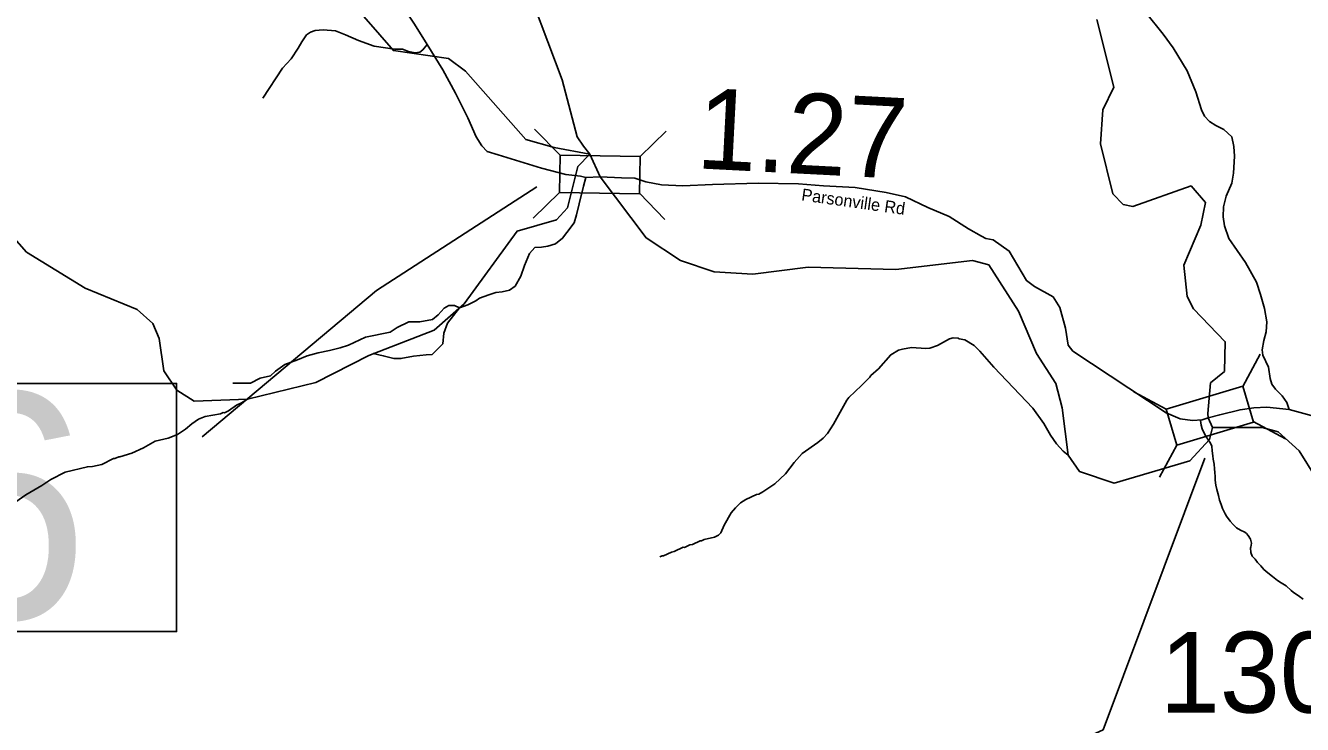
# Model space of a CAD drawing. Extents: x 1248224 to 1454986, y 825081 to 985870.
# Drawn here: x 1300750 to 1308662, y 901429 to 905757 of the extents above; entities that cross this region are included whole.
import ezdxf

# ---------------------------------------------------------------- set-up
doc = ezdxf.new("R2010")
doc.units = 0
for name, color, linetype in [('Exist Hydrographic Creek Single Shore', 7, 'Continuous'), ('Exist Hydrographic Misc Water Feature', 7, 'Continuous'), ('Exist Road Non-System Type 51', 7, 'Continuous'), ('Exist Road Secondary Mileage Hundredths English Label', 7, 'Continuous'), ('Exist Road Secondary Structure Standard Bridge CELL', 7, 'Continuous'), ('Exist Road Secondary Structure Standard Bridge Number Label', 7, 'Continuous'), ('Exist Road Secondary Type 41 Attributed', 7, 'Continuous'), ('Exist Road Secondary Type 51 Attributed', 7, 'Continuous'), ('Exist Road Secondary Type 51 Label', 7, 'Continuous'), ('Exist Road Secondary Type 51 Number Label', 7, 'Continuous')]:
    doc.layers.add(name, color=color, linetype=linetype)

msp = doc.modelspace()

# ---------------------------------------------------------------- linework, layer by layer
at = {"layer": 'Exist Hydrographic Creek Single Shore'}
for points in [[(1304310.6, 904820.9), (1304247, 904960.2), (1304207.5, 905010.9), (1304167.5, 905067.4), (1304075.6, 905420.6), (1303808.5, 906128.4), (1303495.2, 906669.2), (1303356.3, 907192.5), (1303303.2, 907311.5), (1303171.6, 907397.6)], [(1308103.7, 903268.3), (1308084.7, 903193.2), (1307964.7, 903061), (1307494.7, 902922.7), (1307279.7, 902996), (1307209.7, 903095.9), (1307172.7, 903388.7), (1307133.7, 903540.5), (1307013.7, 903726.8), (1306902.6, 903988.4), (1306717.7, 904274.4), (1306617.6, 904302.7), (1306141.7, 904246.6), (1305599.6, 904260.7), (1305256.6, 904218.3), (1305015.6, 904233), (1304808.6, 904302.8), (1304594.6, 904441.8), (1304310.6, 904820.9)], [(1308078, 903328.5), (1308075.9, 903354.2), (1308092.7, 903544.3), (1308177.7, 903614.8), (1308182.7, 903798.5), (1308175.4, 903806.1)], [(1308103.7, 903268.3), (1308078, 903328.5)], [(1309612, 901427.1), (1309422.7, 901551.2), (1309263.8, 901889.2), (1309225.8, 902047.6), (1309237.8, 902224.6), (1309323.8, 902331.2), (1309306.8, 902656.5), (1309333.7, 902754.4), (1309301.7, 902824), (1308852.8, 902882.4), (1308746.8, 902953.4), (1308641.7, 903122.9), (1308511.7, 903240.5), (1308411.7, 903268.7), (1308103.7, 903268.3)]]:
    msp.add_lwpolyline(points, dxfattribs=at)
at = {"layer": 'Exist Hydrographic Misc Water Feature'}
msp.add_line((1304247, 904960.2), (1304171.5, 904883.6), dxfattribs=at)
for points in [[(1304247, 904960.2), (1304025.6, 905001.5), (1303850.5, 905050.9), (1303476.5, 905475.2), (1303369.6, 905553), (1303029.5, 905602.4), (1302761.5, 905909.9), (1302058.5, 906176.7), (1301993.5, 906269.8), (1301955.5, 906405.3), (1301898.5, 906445.8), (1301382.5, 906518.4), (1301292.5, 906579.4), (1301212.4, 906722.2), (1300623.4, 907242.8), (1300187.4, 907461.7), (1299720.4, 907858.5), (1299520.4, 907911.7)], [(1308182.7, 903798.5), (1307986.6, 904002.7), (1307946.7, 904079), (1307926.7, 904273.1), (1308032.7, 904520.5), (1308060.7, 904661.1), (1307971.7, 904764.6), (1307609.7, 904637.3), (1307551.6, 904648.4), (1307486.6, 904715.3), (1307410.6, 905025.4), (1307423.7, 905235.2), (1307493.7, 905375), (1307386.7, 905794)], [(1299447.5, 904919.1), (1299983.5, 904806.7), (1300618.5, 904508.3), (1300756.5, 904354.5), (1301118.5, 904130.6), (1301440.6, 903999.4), (1301538.6, 903912), (1301578.6, 903819.3), (1301606.5, 903618.5), (1301687.5, 903498.7), (1301794.6, 903431), (1302125.6, 903443.6), (1302547.5, 903547.1), (1302876.5, 903714.5), (1303280.6, 903870.6), (1303467.6, 904034.2), (1303795.6, 904484), (1304038.6, 904554.6), (1304107.6, 904628.7), (1304171.5, 904883.6)], [(1304678.9, 902465.9), (1304695.1, 902473.5), (1304703.1, 902473.2), (1304751.7, 902495.8), (1304767.9, 902499.3), (1304824.6, 902525.7), (1304832.6, 902525.5), (1304865.1, 902540.5), (1304881.2, 902544), (1304929.8, 902566.7), (1304937.8, 902566.4), (1304954, 902574), (1305018.5, 902588.1), (1305042.9, 902601.3), (1305057.3, 902615), (1305078.6, 902662.3), (1305122.8, 902739), (1305147.7, 902770.3), (1305180.6, 902801.4), (1305213.2, 902822.4), (1305278, 902852.5), (1305294.1, 902856), (1305318.5, 902869.3), (1305392, 902919.2), (1305457.7, 902981.3), (1305511.8, 903051.7), (1305561.3, 903106.3), (1305659.3, 903175.4), (1305692, 903202.5), (1305718.9, 903231.7), (1305756.5, 903288.6), (1305838.7, 903438.2), (1305851.2, 903453.7), (1305928.5, 903528.3), (1305980.8, 903580), (1305987.1, 903589.8), (1306034.2, 903630.4), (1306110.7, 903718.2), (1306159.5, 903746.8), (1306183.8, 903754), (1306240, 903762.5), (1306328, 903757.9), (1306352, 903759.2), (1306400.5, 903775.8), (1306473.7, 903817.6), (1306497.9, 903822.9), (1306527.8, 903822.1), (1306533.7, 903817.9), (1306569.5, 903810.8), (1306626.5, 903775.3), (1306661.6, 903740.2), (1306748.8, 903641.8), (1306991.8, 903386.8), (1307059.2, 903292.9), (1307101.1, 903219.7), (1307137.7, 903166.7), (1307178.4, 903121.5), (1307209.7, 903095.9)], [(1300654.1, 902782.1), (1300752, 902851.3), (1300849.7, 902908.4), (1300906.8, 902946.8), (1300996.1, 902992.2), (1301133.1, 903024.3), (1301165.2, 903027.3), (1301221.6, 903039.6), (1301294.6, 903075.5), (1301302.6, 903075.3), (1301326.9, 903086.6), (1301334.9, 903086.4), (1301407.5, 903108.2), (1301480.5, 903142.2), (1301553.7, 903184), (1301634.2, 903201.7), (1301690.9, 903224.1), (1301739.8, 903256.6), (1301780.8, 903291.4), (1301821.6, 903320.3), (1301862.1, 903335), (1301958.6, 903352.2), (1301974.8, 903359.8), (1301982.8, 903359.5), (1302007.2, 903370.9), (1302056.2, 903405.5), (1302088.6, 903420.5), (1302125.6, 903443.6)]]:
    msp.add_lwpolyline(points, dxfattribs=at)
at = {"layer": 'Exist Road Non-System Type 51'}
for points in [[(1302220.8, 905308.2), (1302341.6, 905492.5), (1302395.3, 905552), (1302439.5, 905617.2), (1302460.6, 905657.5), (1302491.2, 905699.8), (1302514.3, 905717), (1302544.9, 905726.6), (1302592.9, 905730.5), (1302669.6, 905724.7), (1302732.9, 905699.8), (1302813.5, 905665.2), (1302909.4, 905630.7), (1303036, 905611.5), (1303085.8, 905611.5), (1303122.3, 905596.1), (1303164.5, 905588.4), (1303193.3, 905592.3), (1303210.5, 905607.6), (1303237.5, 905639.5)], [(1304221.4, 904816.6), (1304206.5, 904762.8), (1304180.6, 904653.3), (1304163.4, 904584.2), (1304149, 904535.3), (1304102.9, 904474.8), (1304077, 904440.3), (1304033.9, 904405.7), (1303985, 904391.3), (1303947.6, 904385.6), (1303904.4, 904382.7), (1303872.8, 904345.3), (1303841.1, 904270.4), (1303818.1, 904204.2), (1303783.6, 904143.7), (1303749, 904117.8), (1303703, 904109.2), (1303662.7, 904103.4), (1303619.6, 904089), (1303562, 904068.9), (1303539, 904051.6), (1303490.1, 904028.6), (1303438.3, 904008.4), (1303363.5, 903913.4), (1303340.5, 903852.9), (1303334.7, 903786.7), (1303311.7, 903763.7), (1303268.6, 903720.5), (1303231.2, 903717.6), (1303153.5, 903709), (1303075.8, 903694.6), (1303032.6, 903694.6), (1302966.5, 903711.8), (1302903.2, 903726.2)], [(1303438.3, 904008.4), (1303406.6, 904023.2), (1303372, 904023.2), (1303343.3, 904006), (1303305.9, 903965.7), (1303271.3, 903936.9), (1303193.7, 903922.5), (1303124.6, 903922.5), (1303052.7, 903887.9), (1303009.5, 903859.1), (1302857, 903827.5), (1302750.6, 903778.5), (1302698.8, 903761.2), (1302632.6, 903744), (1302563.6, 903729.6), (1302494.5, 903712.3), (1302434.1, 903686.4), (1302356.4, 903657.6), (1302298.9, 903617.3), (1302267.2, 903588.5), (1302203.9, 903574.1), (1302143.5, 903542.4), (1302091.7, 903542.4), (1302034.2, 903542.4)], [(1308029.6, 903311.9), (1308033, 903281.8), (1308040.3, 903259.7), (1308049.9, 903237.4), (1308065.4, 903210.9), (1308078.7, 903188.6), (1308092.4, 903170.4), (1308100, 903152.2), (1308101.3, 903124.1), (1308106.6, 903092), (1308108, 903072), (1308115.4, 903039.8), (1308116.6, 903011.8), (1308118.2, 902989.7), (1308119.7, 902963.5), (1308121, 902941.4), (1308124.4, 902911.4), (1308131.7, 902883.2), (1308140.9, 902847), (1308148.1, 902816.8), (1308157.6, 902790.6), (1308166.9, 902766.4), (1308182.3, 902733.9), (1308190, 902717.7), (1308213.2, 902687.2), (1308232.8, 902666.8), (1308252.4, 902646.2), (1308277.9, 902631.7), (1308303.7, 902619), (1308315.5, 902610.7), (1308325.3, 902598.5), (1308340.6, 902576.2), (1308342.5, 902568.2), (1308346.2, 902552.1), (1308341.6, 902526.2), (1308339.6, 902522.2), (1308340.8, 902494.2), (1308350.4, 902472), (1308367.8, 902451.4), (1308383.4, 902431.1), (1308403, 902410.7), (1308422.3, 902388.1), (1308447.9, 902367.5), (1308475.5, 902345), (1308506.8, 902320.1), (1308530.5, 902305.6), (1308560.2, 902286.8), (1308591.4, 902258.2), (1308603.2, 902247.8), (1308642.7, 902220.9), (1308666.4, 902204.3)]]:
    msp.add_lwpolyline(points, dxfattribs=at)
at = {"layer": 'Exist Road Secondary Structure Standard Bridge CELL'}
for p, q in [((1303903.9, 905116.7), (1304061.5, 904954.2)), ((1304557.2, 904945.4), (1304719.7, 905102.9)), ((1303895.3, 904565.1), (1304057.9, 904722.6)), ((1304553.6, 904719.1), (1304711.2, 904556.5)), ((1308292, 903522), (1308399.5, 903721.3)), ((1307617.5, 903488.4), (1307816.7, 903381)), ((1308356.9, 903305.2), (1308556.1, 903197.7)), ((1307775.7, 902959.9), (1307883.1, 903159.1))]:
    msp.add_line(p, q, dxfattribs=at)
for points in [[(1304061.5, 904954.2), (1304557.2, 904946.5), (1304553.6, 904714.9), (1304057.9, 904722.6)], [(1307816.7, 903381), (1308291.7, 903523.1), (1308358.1, 903301.2), (1307883.1, 903159.1)]]:
    msp.add_lwpolyline(points, close=True, dxfattribs=at)
at = {"layer": 'Exist Road Secondary Structure Standard Bridge Number Label'}
for points in [[(1303917.6, 904758.9), (1302924.4, 904116.2), (1301843.5, 903210.6)], [(1308057.3, 903077.8), (1307426.7, 901396.2), (1303082.5, 899434.3)]]:
    msp.add_lwpolyline(points, dxfattribs=at)
msp.add_lwpolyline([(1297969.9, 903540.7), (1301685.8, 903540.7), (1301685.8, 902004.2), (1297969.9, 902004.2)], close=True, dxfattribs=at)
at = {"layer": 'Exist Road Secondary Type 41 Attributed'}
msp.add_lwpolyline([(1308579.5, 903379.1), (1308564.5, 903423.3), (1308536.6, 903464.1), (1308493.7, 903504.9), (1308472.2, 903537.1), (1308461.5, 903571.4), (1308450.8, 903642.3), (1308416.4, 903715.3), (1308412.1, 903749.6), (1308422.9, 903807.6), (1308435.7, 903861.3), (1308440, 903921.4), (1308427.2, 904005.2), (1308401.4, 904091), (1308377.8, 904168.3), (1308309.2, 904290.7), (1308206.3, 904437.9), (1308178.4, 904517.4), (1308169.8, 904573.2), (1308172, 904635.5), (1308189.1, 904699.9), (1308223.5, 904781.5), (1308234.2, 904842.4), (1308240.6, 904947.7), (1308236.3, 905007.8), (1308223.5, 905067.9), (1308174.1, 905113), (1308124.8, 905138.8), (1308086.1, 905162.4), (1308054, 905196.7), (1308036.8, 905235.4), (1308000.3, 905347), (1307946.7, 905478), (1307861.3, 905618.5), (1307799.1, 905704.4), (1307689.7, 905839.7)], dxfattribs=at)
at = {"layer": 'Exist Road Secondary Type 51 Attributed'}
for points in [[(1303052.7, 905917.1), (1303096.6, 905861.1), (1303159.5, 905765.4), (1303237.5, 905639.5), (1303335.7, 905483.3), (1303413.7, 905339.7), (1303489.2, 905186.1), (1303541.9, 905068.5), (1303577.1, 905013.1), (1303609.8, 904977.8), (1303677.8, 904957.7), (1303947.1, 904874.5), (1304098.1, 904834.2), (1304188.7, 904824.2), (1304221.4, 904816.6), (1304310.6, 904820.9)], [(1304310.6, 904820.9), (1304442.8, 904814.1), (1304525.9, 904811.6), (1304593.8, 904788.9), (1304689.5, 904771.3), (1304822, 904763.9), (1305005.7, 904774), (1305290.1, 904781.5), (1305539.3, 904776.5), (1305693.9, 904764), (1305890.2, 904753.9), (1306081.5, 904723.7), (1306202.3, 904696), (1306340.7, 904630.5), (1306473.2, 904575.5), (1306591.5, 904497.5), (1306672.1, 904452.1), (1306698.9, 904438.5), (1306744.8, 904430.5), (1306845, 904360.2), (1306952.3, 904177.7), (1307001.6, 904141.2), (1307117.5, 904076.8), (1307158.2, 904010.2), (1307192.6, 903883.5), (1307209.7, 903778.3), (1307239.5, 903740.3), (1307584.9, 903510.6), (1307816.4, 903358.7), (1307904.3, 903322.2), (1307979.5, 903310.6), (1308040.9, 903316.3), (1308078, 903328.5)], [(1308078, 903328.5), (1308149.5, 903347.1), (1308275.5, 903378), (1308361.3, 903388.7), (1308440.4, 903393), (1308579.5, 903379.1)], [(1308579.5, 903379.1), (1308760.2, 903330.2)]]:
    msp.add_lwpolyline(points, dxfattribs=at)

# ---------------------------------------------------------------- texts
at = {"layer": 'Exist Road Secondary Mileage Hundredths English Label'}
msp.add_text('1.27', height=500, rotation=357.06203, dxfattribs=at).set_placement((1304900.6, 904873.5))
at = {"layer": 'Exist Road Secondary Structure Standard Bridge Number Label'}
msp.add_text('106', height=1400, dxfattribs=at).set_placement((1298020, 902083.3))
at = {"layer": 'Exist Road Secondary Type 51 Label'}
msp.add_text('Parsonville Rd', height=75, rotation=352.00803, dxfattribs=at).set_placement((1305553.8, 904674.7))
at = {"layer": 'Exist Road Secondary Type 51 Number Label'}
msp.add_text('1300', height=500, dxfattribs=at).set_placement((1307777.7, 901502.1))

doc.saveas('drawing.dxf')
